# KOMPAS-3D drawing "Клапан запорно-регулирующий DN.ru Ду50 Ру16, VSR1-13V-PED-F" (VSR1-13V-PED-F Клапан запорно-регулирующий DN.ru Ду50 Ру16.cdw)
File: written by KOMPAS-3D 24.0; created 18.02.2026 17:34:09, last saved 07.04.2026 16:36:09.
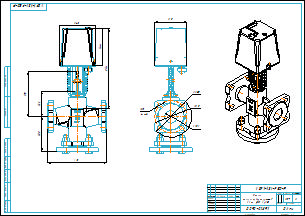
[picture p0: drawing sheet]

Document properties: Автор: R2D2; Форматы листов документа: A2; Полное имя файла: VSR1-13V-PED-F Клапан запорно-регулирующий DN.ru Ду50 Ру16.m3d; Масса: 13.7; Наименование: Клапан запорно-регулирующий DN.ru Ду50 Ру16; Количество листов документа: 1; Примечание: D090-02891

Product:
- Part/product: Клапан запорно-регулирующий DN.ru Ду50 Ру16  | designation VSR1-13V-PED-F
    Масса: 13.7
    Раздел спецификации: Прочие изделия
    Примечание: D090-02891

Views: Вид 1, Спереди
Referenced files in E:\Работа\Зайцев\Солянка\VSR1-13V-PED-F Клапан запорно-регулирующий DN.ru\DN15\DN15 Kv0.16\: VSR1-13V-PED-F Клапан запорно-регулирующий DN.ru Ду15 Ру16.m3d
Referenced files in E:\Работа\Зайцев\Солянка\VSR1-13V-PED-F Клапан запорно-регулирующий DN.ru\DN50\: VSR1-13V-PED-F Клапан запорно-регулирующий DN.ru Ду50 Ру16.m3d
Referenced files in E:\Работа\Зайцев\Для компаса\: чертеж DN.ru А3.cdt
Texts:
  Линейный размер
  VSR1-13V-PED-F
  чертеж DN.ru А3.cdt
  Клапан
  запорно-регулирующий
  DN.ru Ду50 Ру16
  Клапан запорно-регулирующий DN.ru Ду50 Ру16
  VSR1-13V-PED-F Клапан запорно-регулирующий DN.ru Ду50 Ру16
Dimensions and other numbers on the sheet: 0; 3; 2; 4; 143; 144; 314; 230; 135; 100; 175; 1:2; 1; 13,7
